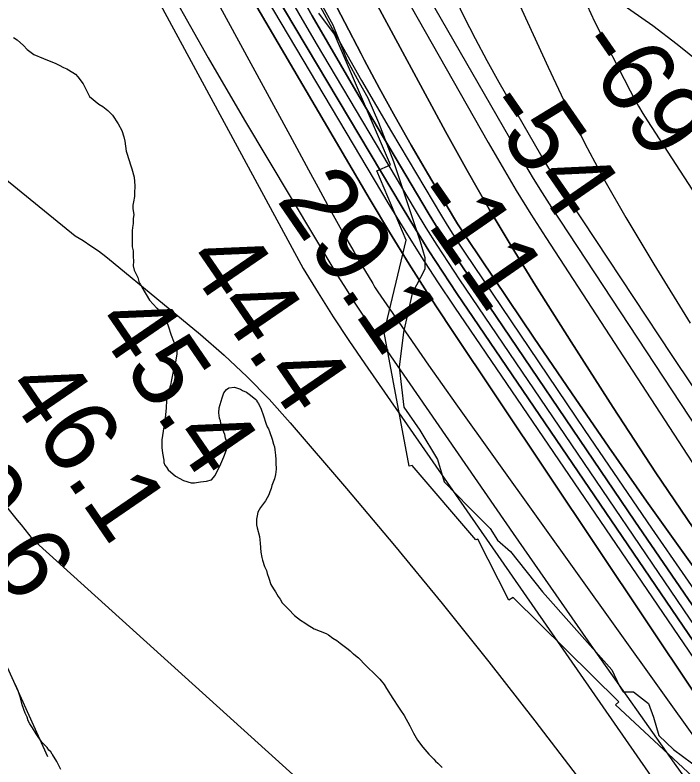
# Model space of a CAD drawing. Extents: x 3172231 to 3210228, y 940198 to 965780.
# Drawn here: x 3189256 to 3189862, y 949077 to 949757 of the extents above; entities that cross this region are included whole.
import ezdxf

# ---------------------------------------------------------------- set-up
doc = ezdxf.new("R2010")
doc.units = 0
for name, color, linetype in [('V-RIVR-EDGE', 7, 'Continuous'), ('V-RIVR-RANG', 7, 'Continuous'), ('V-ROAD-CNTR', 7, 'Continuous'), ('V-RRAP-RVMT', 7, 'Continuous'), ('V-SITE-VEGE', 7, 'Continuous'), ('V-TOPO-DPTH', 7, 'Continuous'), ('V-TOPO-MAJR', 7, 'Continuous'), ('V-TOPO-MINR', 7, 'Continuous'), ('V-TOPO-WATR', 7, 'Continuous')]:
    doc.layers.add(name, color=color, linetype=linetype)

msp = doc.modelspace()

# ---------------------------------------------------------------- linework, layer by layer
at = {"layer": 'V-RIVR-EDGE'}
msp.add_lwpolyline([(3189530.858, 949771.077), (3189543.766, 949747.707), (3189556.134, 949716.041), (3189567.494, 949695.786), (3189575.239, 949681.764), (3189585.037, 949659.439), (3189598.434, 949624.14), (3189622.631, 949551.992), (3189626.744, 949537.46), (3189626.719, 949527.088), (3189615.254, 949504.815), (3189607.389, 949470.087), (3189603.68, 949438.46), (3189607.739, 949402.146), (3189622.209, 949381.366), (3189638.221, 949354.876), (3189644.394, 949334.635), (3189666.639, 949311.76), (3189685.78, 949292.524), (3189692.497, 949282.135), (3189704.399, 949271.733), (3189733.352, 949235.358), (3189761.797, 949203.133), (3189795.931, 949164.67), (3189802.638, 949150.651), (3189806.254, 949144.937), (3189815.589, 949144.914), (3189829.048, 949134.508), (3189833.685, 949122.05), (3189838.311, 949105.443), (3189851.765, 949092.962), (3189876.095, 949074.751)], dxfattribs=at)
at = {"layer": 'V-ROAD-CNTR'}
msp.add_line((3189244.789, 949176.562), (3189285.667, 949086.371), dxfattribs=at)
at = {"layer": 'V-RRAP-RVMT'}
for p, q in [((3189545.005, 949739.417), (3189531.065, 949758.249)), ((3189595.679, 949621.176), (3189545.005, 949739.417)), ((3189583.309, 949615.822), (3189595.679, 949621.176)), ((3189610.053, 949553.026), (3189583.309, 949615.822)), ((3189589.915, 949469.781), (3189610.053, 949553.026)), ((3189612.774, 949348.891), (3189589.915, 949469.781)), ((3189615.477, 949349.366), (3189612.774, 949348.891)), ((3189672.868, 949282.241), (3189615.477, 949349.366)), ((3189674.618, 949283.021), (3189672.868, 949282.241)), ((3189702.627, 949227.914), (3189674.618, 949283.021)), ((3189706.754, 949230.12), (3189702.627, 949227.914)), ((3189802.262, 949135.823), (3189706.754, 949230.12)), ((3189799.138, 949133.182), (3189802.262, 949135.823)), ((3189873.482, 949064.26), (3189799.138, 949133.182))]:
    msp.add_line(p, q, dxfattribs=at)
at = {"layer": 'V-SITE-VEGE'}
for p, q in [((3189254.794, 949736.179), (3189258.126, 949734.141)), ((3189258.126, 949734.141), (3189263.969, 949729.226)), ((3189263.969, 949729.226), (3189267.316, 949725.532)), ((3189267.316, 949725.532), (3189273.155, 949721.03)), ((3189273.155, 949721.03), (3189281.883, 949717.387)), ((3189281.883, 949717.387), (3189293.104, 949712.936)), ((3189293.104, 949712.936), (3189296.018, 949711.306)), ((3189296.018, 949711.306), (3189300.178, 949709.277)), ((3189300.178, 949709.277), (3189303.09, 949708.06)), ((3189303.09, 949708.06), (3189308.501, 949704.8)), ((3189308.501, 949704.8), (3189311.002, 949703.165)), ((3189311.002, 949703.165), (3189313.095, 949700.702)), ((3189313.095, 949700.702), (3189317.707, 949694.535)), ((3189317.707, 949694.535), (3189323.611, 949682.995)), ((3189323.611, 949682.995), (3189331.957, 949676.033)), ((3189331.957, 949676.033), (3189335.702, 949674)), ((3189335.702, 949674), (3189340.292, 949670.315)), ((3189340.292, 949670.315), (3189344.472, 949666.213)), ((3189344.472, 949666.213), (3189349.512, 949658.394)), ((3189349.512, 949658.394), (3189352.881, 949652.213)), ((3189352.881, 949652.213), (3189354.593, 949646.434)), ((3189354.593, 949646.434), (3189355.455, 949642.714)), ((3189355.455, 949642.714), (3189356.783, 949633.617)), ((3189356.783, 949633.617), (3189359.771, 949624.123)), ((3189359.771, 949624.123), (3189360.203, 949622.056)), ((3189360.203, 949622.056), (3189361.903, 949617.518)), ((3189361.903, 949617.518), (3189364.043, 949610.086)), ((3189364.043, 949610.086), (3189364.528, 949602.221)), ((3189364.528, 949602.221), (3189364.178, 949595.594)), ((3189364.204, 949592.696), (3189363.422, 949587.72)), ((3189364.178, 949595.594), (3189364.204, 949592.696)), ((3189363.422, 949587.72), (3189362.621, 949584.813)), ((3189362.621, 949584.813), (3189362.648, 949581.916)), ((3189362.648, 949581.916), (3189363.531, 949576.128)), ((3189363.531, 949576.128), (3189363.146, 949572.81)), ((3189363.146, 949572.81), (3189363.191, 949568.257)), ((3189362.396, 949564.524), (3189362.009, 949561.622)), ((3189363.191, 949568.257), (3189362.396, 949564.524)), ((3189362.009, 949561.622), (3189362.144, 949547.13)), ((3189362.144, 949547.13), (3189363.008, 949543.411)), ((3189363.008, 949543.411), (3189363.035, 949540.513)), ((3189363.035, 949540.513), (3189363.054, 949538.443)), ((3189363.054, 949538.443), (3189363.506, 949534.308)), ((3189363.506, 949534.308), (3189363.168, 949529.841)), ((3189363.168, 949529.841), (3189364.02, 949525.946)), ((3189364.02, 949525.946), (3189367.166, 949519.267)), ((3189367.166, 949519.267), (3189368.52, 949514.467)), ((3189368.52, 949514.467), (3189369.585, 949512.974)), ((3189369.585, 949512.974), (3189371, 949510.739)), ((3189371, 949510.739), (3189377.693, 949498.84)), ((3189377.693, 949498.84), (3189384.494, 949491.711)), ((3189384.494, 949491.711), (3189388.424, 949487.216)), ((3189388.424, 949487.216), (3189390.923, 949484.222)), ((3189390.923, 949484.222), (3189392.346, 949482.354)), ((3189392.346, 949482.354), (3189394.759, 949475.694)), ((3189394.759, 949475.694), (3189397.495, 949467.191)), ((3189397.495, 949467.191), (3189399.573, 949462.005)), ((3189399.573, 949462.005), (3189402.369, 949456.07)), ((3189402.369, 949456.07), (3189402.668, 949453.129)), ((3189402.607, 949450.561), (3189401.736, 949444.712)), ((3189402.668, 949453.129), (3189402.607, 949450.561)), ((3189401.736, 949444.712), (3189398.891, 949433.036)), ((3189398.891, 949433.036), (3189397.646, 949426.831)), ((3189396.8, 949422.079), (3189395.606, 949418.071)), ((3189397.646, 949426.831), (3189396.8, 949422.079)), ((3189394.82, 949415.888), (3189393.661, 949413.349)), ((3189395.606, 949418.071), (3189394.82, 949415.888)), ((3189443.495, 949410.711), (3189445.066, 949415.077)), ((3189445.066, 949415.077), (3189447.343, 949418.323)), ((3189447.343, 949418.323), (3189449.577, 949419.738)), ((3189449.577, 949419.738), (3189454.728, 949420.353)), ((3189454.728, 949420.353), (3189460.186, 949418.389)), ((3189460.186, 949418.389), (3189461.992, 949417.246)), ((3189461.992, 949417.246), (3189465.626, 949415.694)), ((3189465.626, 949415.694), (3189469.232, 949413.039)), ((3189393.182, 949408.589), (3189393.01, 949401.255)), ((3189393.661, 949413.349), (3189393.182, 949408.589)), ((3189440.714, 949401.603), (3189443.495, 949410.711)), ((3189469.232, 949413.039), (3189473.914, 949409.263)), ((3189473.914, 949409.263), (3189474.987, 949408.135)), ((3189474.987, 949408.135), (3189474.971, 949407.401)), ((3189393.01, 949401.255), (3189392.07, 949392.473)), ((3189440.609, 949397.202), (3189440.714, 949401.603)), ((3189474.971, 949407.401), (3189476.394, 949405.532)), ((3189476.394, 949405.532), (3189478.839, 949400.34)), ((3189441.232, 949392.418), (3189440.609, 949397.202)), ((3189478.839, 949400.34), (3189480.902, 949394.421)), ((3189480.902, 949394.421), (3189482.948, 949387.769)), ((3189391.248, 949388.824), (3189390.779, 949384.433)), ((3189392.07, 949392.473), (3189391.248, 949388.824)), ((3189441.902, 949389.834), (3189441.232, 949392.418)), ((3189442.534, 949385.416), (3189441.902, 949389.834)), ((3189482.948, 949387.769), (3189484.336, 949384.435)), ((3189390.779, 949384.433), (3189389.036, 949372.733)), ((3189446.02, 949377.63), (3189442.534, 949385.416)), ((3189484.336, 949384.435), (3189485.393, 949382.575)), ((3189485.393, 949382.575), (3189486.441, 949380.349)), ((3189446.675, 949374.314), (3189446.02, 949377.63)), ((3189447.697, 949370.988), (3189446.675, 949374.314)), ((3189486.441, 949380.349), (3189488.846, 949373.323)), ((3189389.036, 949372.733), (3189388.873, 949365.765)), ((3189447.525, 949363.654), (3189447.697, 949370.988)), ((3189488.846, 949373.323), (3189489.841, 949368.897)), ((3189489.841, 949368.897), (3189490.881, 949366.302)), ((3189388.873, 949365.765), (3189389.485, 949360.615)), ((3189389.485, 949360.615), (3189390.806, 949354.346)), ((3189445.178, 949357.471), (3189447.525, 949363.654)), ((3189490.881, 949366.302), (3189491.187, 949363.728)), ((3189491.187, 949363.728), (3189491.809, 949358.944)), ((3189390.806, 949354.346), (3189390.755, 949352.146)), ((3189441.306, 949348.757), (3189445.178, 949357.471)), ((3189491.809, 949358.944), (3189492.082, 949354.901)), ((3189492.082, 949354.901), (3189492.012, 949351.968)), ((3189390.755, 949352.146), (3189391.803, 949349.92)), ((3189391.803, 949349.92), (3189393.227, 949348.052)), ((3189393.227, 949348.052), (3189394.634, 949345.451)), ((3189438.619, 949343.684), (3189441.306, 949348.757)), ((3189492.012, 949351.968), (3189492.241, 949346.092)), ((3189394.634, 949345.451), (3189401.472, 949339.787)), ((3189401.472, 949339.787), (3189408.718, 949335.949)), ((3189434.045, 949336.452), (3189437.074, 949340.417)), ((3189437.074, 949340.417), (3189438.619, 949343.684)), ((3189491.764, 949341.335), (3189490.935, 949337.319)), ((3189492.241, 949346.092), (3189491.764, 949341.335)), ((3189408.718, 949335.949), (3189415.642, 949333.952)), ((3189415.642, 949333.952), (3189418.577, 949333.882)), ((3189418.577, 949333.882), (3189424.102, 949334.853)), ((3189424.102, 949334.853), (3189429.253, 949335.465)), ((3189429.253, 949335.465), (3189434.045, 949336.452)), ((3189490.935, 949337.319), (3189488.596, 949331.502)), ((3189487.793, 949328.586), (3189486.624, 949325.68)), ((3189488.596, 949331.502), (3189487.793, 949328.586)), ((3189485.831, 949323.128), (3189482.767, 949317.699)), ((3189486.624, 949325.68), (3189485.831, 949323.128)), ((3189482.767, 949317.699), (3189478.221, 949311.567)), ((3189475.919, 949307.219), (3189475.108, 949303.936)), ((3189478.221, 949311.567), (3189475.919, 949307.219)), ((3189474.672, 949301.014), (3189474.551, 949295.877)), ((3189475.108, 949303.936), (3189474.672, 949301.014)), ((3189474.551, 949295.877), (3189475.222, 949293.293)), ((3189475.222, 949293.293), (3189477.234, 949285.175)), ((3189477.234, 949285.175), (3189477.83, 949279.291)), ((3189477.83, 949279.291), (3189478.372, 949271.205)), ((3189478.372, 949271.205), (3189479.361, 949266.413)), ((3189479.361, 949266.413), (3189480.033, 949263.828)), ((3189480.033, 949263.828), (3189481.737, 949258.286)), ((3189481.737, 949258.286), (3189483.486, 949254.575)), ((3189483.486, 949254.575), (3189484.16, 949251.993)), ((3189484.16, 949251.993), (3189485.886, 949247.549)), ((3189485.886, 949247.549), (3189487.592, 949242.005)), ((3189487.592, 949242.005), (3189490.064, 949237.911)), ((3189490.064, 949237.911), (3189491.838, 949235.302)), ((3189491.838, 949235.302), (3189494.31, 949231.208)), ((3189494.31, 949231.208), (3189496.083, 949228.597)), ((3189496.083, 949228.597), (3189497.839, 949225.254)), ((3189497.839, 949225.254), (3189505.009, 949218.115)), ((3189505.009, 949218.115), (3189507.515, 949215.485)), ((3189507.515, 949215.485), (3189508.949, 949213.986)), ((3189508.949, 949213.986), (3189514.354, 949209.825)), ((3189514.354, 949209.825), (3189518.327, 949207.162)), ((3189518.327, 949207.162), (3189520.491, 949205.645)), ((3189520.491, 949205.645), (3189526.64, 949201.827)), ((3189526.64, 949201.827), (3189537.545, 949197.539)), ((3189537.545, 949197.539), (3189539.72, 949196.386)), ((3189539.72, 949196.386), (3189543.683, 949193.359)), ((3189543.683, 949193.359), (3189547.308, 949191.44)), ((3189547.308, 949191.44), (3189550.183, 949188.804)), ((3189550.183, 949188.804), (3189557.394, 949183.498)), ((3189557.394, 949183.498), (3189559.193, 949181.986)), ((3189559.193, 949181.986), (3189561.71, 949179.727)), ((3189561.71, 949179.727), (3189562.432, 949179.342)), ((3189562.432, 949179.342), (3189564.233, 949177.833)), ((3189564.233, 949177.833), (3189566.748, 949175.572)), ((3189566.748, 949175.572), (3189573.559, 949168.807)), ((3189573.559, 949168.807), (3189582.886, 949159.784)), ((3189582.886, 949159.784), (3189586.109, 949156.407)), ((3189586.109, 949156.407), (3189590.031, 949151.545)), ((3189256.873, 949150.566), (3189255.126, 949154.279)), ((3189258.96, 949145.751), (3189256.873, 949150.566)), ((3189590.031, 949151.545), (3189592.145, 949147.826)), ((3189260.69, 949141.307), (3189258.96, 949145.751)), ((3189592.145, 949147.826), (3189597.803, 949138.886)), ((3189261.356, 949138.356), (3189260.69, 949141.307)), ((3189262.702, 949133.188), (3189261.356, 949138.356)), ((3189597.803, 949138.886), (3189603.124, 949131.059)), ((3189265.462, 949125.785), (3189262.702, 949133.188)), ((3189603.124, 949131.059), (3189604.898, 949128.447)), ((3189267.209, 949122.076), (3189265.462, 949125.785)), ((3189604.898, 949128.447), (3189608.084, 949123.604)), ((3189608.084, 949123.604), (3189613.372, 949114.308)), ((3189268.231, 949118.748), (3189267.209, 949122.076)), ((3189269.638, 949116.147), (3189268.231, 949118.748)), ((3189272.118, 949112.42), (3189269.638, 949116.147)), ((3189275.291, 949106.843), (3189272.118, 949112.42)), ((3189613.372, 949114.308), (3189616.514, 949107.629)), ((3189280.617, 949099.38), (3189275.291, 949106.843)), ((3189616.514, 949107.629), (3189620.037, 949101.309)), ((3189285.273, 949094.502), (3189280.617, 949099.38)), ((3189620.037, 949101.309), (3189625.023, 949094.954)), ((3189286.686, 949092.265), (3189285.273, 949094.502)), ((3189288.488, 949090.756), (3189286.686, 949092.265)), ((3189289.901, 949088.522), (3189288.488, 949090.756)), ((3189290.259, 949088.147), (3189289.901, 949088.522)), ((3189625.023, 949094.954), (3189630.377, 949088.591)), ((3189630.377, 949088.591), (3189633.25, 949085.955)), ((3189294.147, 949081.818), (3189290.259, 949088.147)), ((3189297.651, 949074.765), (3189294.147, 949081.818)), ((3189633.25, 949085.955), (3189635.04, 949084.079)), ((3189635.04, 949084.079), (3189636.464, 949082.212)), ((3189636.464, 949082.212), (3189638.62, 949080.328)), ((3189638.62, 949080.328), (3189642.569, 949076.565))]:
    msp.add_line(p, q, dxfattribs=at)
at = {"layer": 'V-TOPO-DPTH'}
for points in [[(3189915.067, 949077.497), (3189649.664, 949474.253), (3189631.006, 949502.688), (3189612.687, 949531.337), (3189594.88, 949560.305), (3189577.413, 949589.487), (3189405.937, 949881.818), (3189331.147, 950012.33), (3189258.142, 950143.81), (3189187.815, 950276.741), (3189119.273, 950410.64), (3188985.477, 950678.67), (3188985.176, 950679.281), (3188984.292, 950681.125), (3188411.405, 951908.58)], [(3189510.493, 949901.786), (3189645.603, 949651.359), (3189665.082, 949616.114), (3189685.03, 949581.142), (3189705.681, 949546.582), (3189726.802, 949512.295), (3189759, 949461.191), (3189797.026, 949401.861), (3189835.656, 949342.933), (3189875.193, 949284.61)], [(3189875.193, 949284.61), (3189835.656, 949342.933), (3189797.026, 949401.861), (3189759, 949461.191), (3189726.802, 949512.295), (3189705.681, 949546.582), (3189685.03, 949581.142), (3189665.082, 949616.114), (3189645.603, 949651.359), (3189510.493, 949901.786)], [(3189570.205, 949842.339), (3189684.111, 949641.364), (3189696.683, 949619.651), (3189709.519, 949598.099), (3189722.751, 949576.787), (3189736.246, 949555.636), (3190132.964, 948946.329)], [(3189570.205, 949842.339), (3189684.111, 949641.364), (3189696.683, 949619.651), (3189709.519, 949598.099), (3189722.751, 949576.787), (3189736.246, 949555.636), (3190132.964, 948946.329)], [(3189901.938, 949174.82), (3189816.707, 949299.062), (3189660.4, 949529.806), (3189652.546, 949541.625), (3189644.834, 949553.533), (3189637.336, 949565.577), (3189629.979, 949577.711), (3189564.322, 949688.197), (3189524.875, 949755.992), (3189486.27, 949824.252)], [(3189486.27, 949824.252), (3189524.875, 949755.992), (3189564.322, 949688.197), (3189629.979, 949577.711), (3189637.336, 949565.577), (3189644.834, 949553.533), (3189652.546, 949541.625), (3189660.4, 949529.806), (3189816.707, 949299.062), (3189901.938, 949174.82)], [(3190089.376, 948867.77), (3189655.811, 949505.052), (3189643.007, 949524.249), (3189630.441, 949543.598), (3189618.233, 949563.174), (3189606.263, 949582.902), (3189490.658, 949777.444)], [(3189490.658, 949777.444), (3189606.263, 949582.902), (3189618.233, 949563.174), (3189630.441, 949543.598), (3189643.007, 949524.249), (3189655.811, 949505.052), (3190089.376, 948867.77)], [(3189539.602, 949778.636), (3189554.453, 949750.017), (3189569.344, 949721.419), (3189572.04, 949716.253), (3189585.822, 949690.37), (3189599.888, 949664.645), (3189614.376, 949639.156), (3189629.148, 949613.824), (3189653.694, 949572.519), (3189656.443, 949567.983), (3189659.242, 949563.479), (3189662.119, 949559.023), (3189665.046, 949554.6), (3189725.79, 949464.509), (3189759.332, 949415.207), (3189793.147, 949366.094), (3189827.372, 949317.266), (3189861.87, 949268.627), (3190340.799, 948599.332)], [(3190340.799, 948599.332), (3189861.87, 949268.627), (3189827.372, 949317.266), (3189793.147, 949366.094), (3189759.332, 949415.207), (3189725.79, 949464.509), (3189665.046, 949554.6), (3189662.119, 949559.023), (3189659.242, 949563.479), (3189656.443, 949567.983), (3189653.694, 949572.519), (3189629.148, 949613.824), (3189614.376, 949639.156), (3189599.888, 949664.645), (3189585.822, 949690.37), (3189572.04, 949716.253), (3189569.344, 949721.419), (3189554.453, 949750.017), (3189539.602, 949778.636)]]:
    msp.add_lwpolyline(points, dxfattribs=at)
at = {"layer": 'V-TOPO-MAJR'}
for points in [[(3188818.55, 950890.161), (3188903.701, 950706.673), (3188917.3, 950677.732), (3188931.083, 950648.881), (3188945.143, 950620.163), (3188959.387, 950591.534), (3188987.934, 950534.839), (3189009.775, 950491.392), (3189031.575, 950447.925), (3189053.317, 950404.428), (3189075.02, 950360.912), (3189096.296, 950317.197), (3189117.042, 950273.239), (3189136.994, 950228.915), (3189516.871, 949527.552), (3189530.283, 949505.679), (3189543.984, 949483.993), (3189558.119, 949462.587), (3189572.544, 949441.368), (3189951.891, 948895.282)], [(3190153.584, 948956.938), (3189741.723, 949582.816), (3189733.346, 949595.802), (3189725.129, 949608.886), (3189717.151, 949622.118), (3189709.332, 949635.448), (3189630.467, 949772.757)]]:
    msp.add_lwpolyline(points, dxfattribs=at)
at = {"layer": 'V-TOPO-MINR'}
for points in [[(3188411.405, 951908.58), (3188984.292, 950681.125), (3188985.176, 950679.281), (3188985.477, 950678.67), (3189119.273, 950410.64), (3189187.815, 950276.741), (3189258.142, 950143.81), (3189331.147, 950012.33), (3189405.937, 949881.818), (3189577.413, 949589.487), (3189594.88, 949560.305), (3189612.687, 949531.337), (3189631.006, 949502.688), (3189649.664, 949474.253), (3189915.067, 949077.497)], [(3189232.397, 950809.962), (3189738.345, 949709.462), (3189754.512, 949674.788), (3189771.491, 949640.534), (3189789.688, 949606.912), (3189808.698, 949573.71), (3189833.828, 949531.592), (3189866.632, 949478.051)], [(3188350.65, 950314.427), (3188360.348, 950298.59), (3188371.754, 950283.624), (3189116.452, 949450.524), (3189128.481, 949437.392), (3189140.717, 949424.462), (3189153.265, 949411.833), (3189166.02, 949399.405), (3189181.307, 949384.869), (3189186.593, 949379.879), (3189191.902, 949374.915), (3189197.246, 949369.99), (3189202.615, 949365.09), (3189207.88, 949360.094), (3189212.983, 949354.946), (3189217.845, 949349.568), (3189222.546, 949344.038), (3189258.278, 949299.984), (3189261.644, 949295.826), (3189265.004, 949291.662), (3189268.356, 949287.492), (3189271.701, 949283.317), (3190177.18, 948464.824)], [(3188492.239, 950223.658), (3189310.522, 949557.144), (3189317.728, 949552.777), (3189324.779, 949548.173), (3189331.7, 949543.389), (3189338.426, 949538.333), (3189345.021, 949533.097), (3189423.87, 949467.895), (3189445.344, 949449.186), (3189466.133, 949429.782), (3189485.897, 949409.333), (3189504.976, 949388.189), (3189555.876, 949328.772), (3189599.459, 949277.045), (3189642.466, 949224.851), (3189684.61, 949171.958), (3189726.179, 949118.6), (3190220.44, 948473.312)], [(3189300.515, 950023.6), (3189504.638, 949648.049), (3189513.19, 949632.311), (3189521.739, 949616.571), (3189530.283, 949600.828), (3189538.825, 949585.084), (3189543.839, 949575.839), (3189549.942, 949564.757), (3189556.14, 949553.728), (3189562.48, 949542.781), (3189568.914, 949531.887), (3189579.679, 949513.927), (3189580.818, 949512.065), (3189581.98, 949510.217), (3189584.391, 949506.577), (3189605.959, 949475.073), (3189618.031, 949457.557), (3189630.176, 949440.092), (3189642.43, 949422.704), (3189654.756, 949405.366), (3190276.246, 948537.001)], [(3189510.493, 949901.786), (3189645.603, 949651.359), (3189665.082, 949616.114), (3189685.03, 949581.142), (3189705.681, 949546.582), (3189726.802, 949512.295), (3189759, 949461.191), (3189797.026, 949401.861), (3189835.656, 949342.933), (3189875.193, 949284.61)], [(3189570.205, 949842.339), (3189684.111, 949641.364), (3189696.683, 949619.651), (3189709.519, 949598.099), (3189722.751, 949576.787), (3189736.246, 949555.636), (3190132.964, 948946.329)], [(3189451.182, 949826.523), (3189594.41, 949585.497), (3189608.687, 949561.974), (3189623.252, 949538.636), (3189638.25, 949515.573), (3189653.537, 949492.693), (3190218.667, 948663.708)], [(3189486.27, 949824.252), (3189524.875, 949755.992), (3189564.322, 949688.197), (3189629.979, 949577.711), (3189637.336, 949565.577), (3189644.834, 949553.533), (3189652.546, 949541.625), (3189660.4, 949529.806), (3189816.707, 949299.062), (3189901.938, 949174.82)], [(3189478.519, 949817.121), (3189528.691, 949730.801), (3189618.12, 949580.307), (3189627.783, 949564.375), (3189637.636, 949548.564), (3189647.772, 949532.934), (3189658.098, 949517.424), (3189955.56, 949079.272)], [(3189517.298, 949791.746), (3189543.047, 949744.428), (3189569.617, 949697.566), (3189596.736, 949651.009), (3189641.836, 949575.115), (3189646.888, 949566.779), (3189652.036, 949558.504), (3189657.328, 949550.321), (3189662.715, 949542.198), (3189771.537, 949381.185), (3189831.843, 949292.906), (3189892.729, 949205.034)], [(3189876.664, 949712.573), (3189855.114, 949730.082), (3189832.864, 949746.779), (3189776.394, 949786.654), (3189772.773, 949787.228), (3189770.028, 949786.603), (3189768.597, 949784.178), (3189768.042, 949780.554), (3189770.666, 949772.913), (3189773.54, 949765.376), (3189776.792, 949757.993), (3189780.293, 949750.713), (3189812.427, 949688.01), (3189816.112, 949681.086), (3189819.936, 949674.243), (3189823.969, 949667.521), (3189828.143, 949660.88), (3189971.35, 949440.608)], [(3189399.059, 949774.968), (3189430.983, 949718.014), (3189463.86, 949661.578), (3189548.276, 949520.739), (3189555.547, 949508.869), (3189562.967, 949497.094), (3189570.612, 949485.464), (3189578.406, 949473.931), (3189706.609, 949288.094), (3189779.133, 949184.083), (3189852.346, 949080.564), (3189926.591, 948977.784)], [(3189539.602, 949778.636), (3189554.453, 949750.017), (3189569.344, 949721.419), (3189572.04, 949716.253), (3189585.822, 949690.37), (3189599.888, 949664.645), (3189614.376, 949639.156), (3189629.148, 949613.824), (3189653.694, 949572.519), (3189656.443, 949567.983), (3189659.242, 949563.479), (3189662.119, 949559.023), (3189665.046, 949554.6), (3189725.79, 949464.509), (3189759.332, 949415.207), (3189793.147, 949366.094), (3189827.372, 949317.266), (3189861.87, 949268.627), (3190340.799, 948599.332)], [(3189652.435, 949775.654), (3189662.146, 949755.448), (3189672.2, 949735.421), (3189682.77, 949715.661), (3189693.682, 949696.078), (3189731.376, 949630.452), (3189734.977, 949624.317), (3189738.653, 949618.228), (3189742.442, 949612.209), (3189746.306, 949606.236), (3189850.17, 949448.95), (3189906.574, 949364.75)]]:
    msp.add_lwpolyline(points, dxfattribs=at)
at = {"layer": 'V-TOPO-WATR'}
msp.add_lwpolyline([(3189490.658, 949777.444), (3189606.263, 949582.902), (3189618.233, 949563.174), (3189630.441, 949543.598), (3189643.007, 949524.249), (3189655.811, 949505.052), (3190089.376, 948867.77)], dxfattribs=at)

# ---------------------------------------------------------------- texts
at = {"layer": 'V-RIVR-RANG'}
for s, rotation, p in [('-69', 304.692222, (3189760.52, 949728.082)), ('-54', 304.692222, (3189676.991, 949673.053)), ('29.1', 304.448326, (3189492.095, 949589.637)), ('-11', 304.692222, (3189611.479, 949591.998)), ('44.4', 304.448326, (3189408.424, 949534.83)), ('45.4', 304.448326, (3189326.096, 949478.066)), ('46.1', 304.448326, (3189245.112, 949419.345)), ('50.6', 304.448326, (3189160.397, 949366.061))]:
    msp.add_text(s, height=67, rotation=rotation, dxfattribs=at).set_placement(p)

doc.saveas('drawing.dxf')
